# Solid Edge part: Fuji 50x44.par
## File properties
Title: Lines 50x44
Author: DESYS
Template: Parte SCARABEO.par
Last saved by: i.fialdini
Revision: 14
Application: Solid Edge
Stile della faccia: Model Default
Coef. of Thermal Exp: 0.0
Thermal Conductivity: 0.0
Specific Heat: 0.0
Modulus of Elasticity: 0.0
Poisson's Ratio: 0.0
Yield Stress: 0.0
Ultimate Stress: 0.0
Elongation: 0.0
Tipo di contenuto documento: 0
Precisione: 0.990
Document Number: 6001
Revision: 0
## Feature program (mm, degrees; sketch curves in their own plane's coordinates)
sketch for "unnamed Protrusion 1" plane through (0, 0, 0) normal (0, -1, 0) x-axis (1, 0, 0)
extrude "unnamed Protrusion 1" add finite 140 along -normal
fillet "Rotondo_22" radius 35
lofted cutout "unnamed LoftedCutout 1"
fillet "Rotondo_26" radius 60
sketch for "unnamed Cutout 1" plane through (0, 0, 0) normal (0, -1, 0) x-axis (-1, 0, 0)
  arc centre (11, 0) radius 229 from (-210, 60) to (-210, -60) ccw
  line (-210, -60) -> (-210, -157.5)
  arc centre (-175, -157.5) radius 35 from (-175, -192.5) to (-210, -157.5) cw
  line (-175, -192.5) -> (175, -192.5)
  arc centre (175, -157.5) radius 35 from (210, -157.5) to (175, -192.5) cw
  line (210, -157.5) -> (210, 142.5)
  arc centre (175, 142.5) radius 35 from (175, 177.5) to (210, 142.5) cw
  line (175, 177.5) -> (-175, 177.5)
  arc centre (-175, 142.5) radius 35 from (-210, 142.5) to (-175, 177.5) cw
  line (-210, 142.5) -> (-210, 60)
extrude "unnamed Cutout 1" cut along +normal
fillet "Rotondo_27" radius 10
sketch for "unnamed Protrusion 2" plane through (0, 25, 0) normal (0, -1, 0) x-axis (0, 0, -1)
extrude "unnamed Protrusion 2" add to key point along +normal
sketch for "Foro_9" plane through (0, 45, 0) normal (0, 1, 0) x-axis (-1, 0, 0)
hole "Foro_9" diameter 50 through
sketch for "ProtrusioneEstrusa_8" plane through (0, 0, 0) normal (0, 0, 1) x-axis (1, 0, 0)
extrude "ProtrusioneEstrusa_8" add finite 50 symmetric
fillet "Rotondo_28" radius 10
fillet "Rotondo_29" radius 5
fillet "Rotondo_33" radius 10
fillet "Rotondo_34" radius 5
fillet "Rotondo_35" radius 5
sketch for "unnamed Cutout 2" plane through (0, 67.5, 217.5) normal (0, 0, 1) x-axis (1, 0, 0)
extrude "unnamed Cutout 2" cut through along -normal
fillet "Rotondo_36" radius 10
fillet "Rotondo_38" radius 5
sketch for "unnamed Cutout 3" #1 plane through (0, 67.5, 217.5) normal (0, 0, 1) x-axis (1, 0, 0)
sketch for "unnamed Cutout 3" #2 plane through (0, 67.5, 217.5) normal (0, 0, 1) x-axis (1, 0, 0)
extrude "unnamed Cutout 3" cut through along -normal
sketch for "Foro_10" plane through (0, 67.5, 217.5) normal (0, 0, 1) x-axis (1, 0, 0)
  hole centre (-200, 42.5) bore radius 7.5
hole "Foro_10" finite
sketch for "unnamed Hole 1" plane through (0, 67.5, 217.5) normal (0, 0, 1) x-axis (1, 0, 0)
hole "unnamed Hole 1" finite
pattern "unnamed Pattern 1" of "Foro_10", "unnamed Hole 1"
fillet "Rotondo_39" radius 5
Other named dimensions: "SuperficieOffset_2": Distance = 20 mm
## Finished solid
Body 1: sheet body, 4 faces, 14 edges, 12 vertices.
  Faces by surface: plane 2, blend 1, offset 1
  Edges by curve: intersection 6, circle 4, line 4
Body 2: solid body, 128 faces, 287 edges, 160 vertices.
  Faces by surface: cylinder 49, plane 28, torus 23, blend 22, sphere 4, offset 1, spline 1
  Edges by curve: circle 132, line 102, intersection 53
Bounding box of the edges (mm; curved faces can reach further): 500.000 x 140.000 x 435.000, from (-250, 0, -217.5) to (250, 140, 217.5).
Cylindrical faces by radius (mm): R5 x21, R7.5 x2, R10 x12, R25 x1, R35 x11, R133.6111 x1, R229 x1
Toroidal faces (ring radius, tube radius in mm): R10 r5 x2, R25 r10 x4, R30 r5 x13, R35 r10 x1, R40 r5 x1, R138.6111 r5 x1, R219 r10 x1
Spherical faces by radius (mm): R5 x4
Planar faces by outward normal: +x 2, +y 4, +z 5, -x 3, -y 9, -z 3, oblique 2
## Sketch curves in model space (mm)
arc centre (0, 31.2658, -204.1392) radius 110 from (0, 45, -95) through (0, 108.0036, -125.3274) to (0, 140, -187.5)
arc centre (0, 31.2658, 204.1392) radius 110 from (0, 45, 95) through (0, 108.0036, 125.3274) to (0, 140, 187.5)
ellipse centre (0, 140, 0) radii 197.5, 187.5
arc centre (-212.5652, 20.9494, 0) radius 120 from (-95, 45, 0) through (-133.6338, 111.3365, 0) to (-197.5, 140, 0)
arc centre (212.5652, 20.9494, 0) radius 120 from (95, 45, 0) through (133.6338, 111.3365, 0) to (197.5, 140, 0)
circle centre (0, 45, 0) radius 95
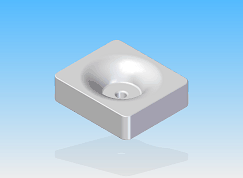
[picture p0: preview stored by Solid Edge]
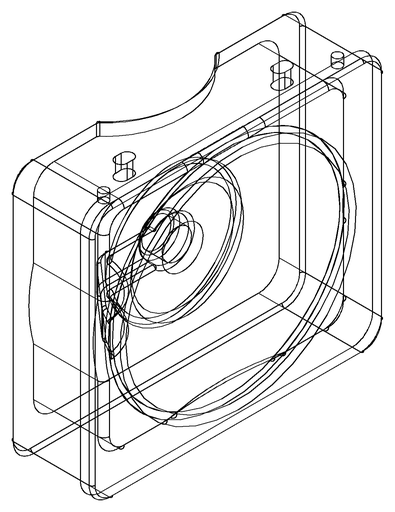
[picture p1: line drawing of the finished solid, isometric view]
